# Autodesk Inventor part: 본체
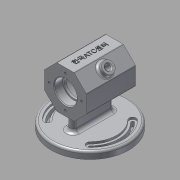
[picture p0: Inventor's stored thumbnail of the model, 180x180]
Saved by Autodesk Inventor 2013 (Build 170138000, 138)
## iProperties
Created: 2017-06
Part Number: 본체
Material: 알루미늄 6061
Document SubType Name: Modeling
Designer: Administrator
Density: 2.71 g/cm^3
Mass: 656.312 g
Surface Area: 514.605 cm^2
Volume: 242.182 cm^3
Author: Administrator
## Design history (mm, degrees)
sketch "스케치2"
  geometry: L1 (0, 0)-(70, 0); L2 (0, 17)-(0, 30); L3 (0, 30)-(70, 30); L4 (70, 17)-(70, 30); L5 (1, 16)-(11.7, 16); L6 (12, 15.7)-(12, 14); L7 (12, 14)-(15, 14); L8 (15, 14)-(15, 22); L9 (18, 25)-(52, 25); L10 (55, 22)-(55, 14); L11 (55, 14)-(58, 14); L12 (58, 14)-(58, 15.7); L13 (58.3, 16)-(69, 16); L14 (0, 17)-(1, 16); L15 (70, 17)-(69, 16); A1 r 3 centre (52, 22) between (55, 22) and (52, 25); A2 r 3 centre (18, 22) between (18, 25) and (15, 22); A3 r 0.3 centre (58.3, 15.7) between (58.3, 16) and (58, 15.7); A4 r 0.3 centre (11.7, 15.7) between (12, 15.7) and (11.7, 16); 8 further points
  constraints: 30 end point, 14 point on line, 8 point on circle, 8 tangent, 6 parallel, 6 perpendicular, 4 centre point, 1 collinear, 1 equal radius, 1 horizontal
  dimensions: "d0" = 70 distance of L1.start L1.end; "d1" = 60 diameter of L3 L1; "d2" = 32 diameter of L5 L1; "d3" = 28 diameter of L7 L1; "d4" = 12 distance from line of point (0, 16) L6; "d5" = 12 distance of point (70, 16) point (58, 16); "d6" = 32 diameter of L13 L1; "d7" = 28 diameter of L11 L1; "d9" = 40 distance between parallel lines of L10 L8; "d10" = 3 radius of A1; "d11" = 1 distance of L2.start point (0, 16); "d12" = 1 distance of L5.start point (0, 16) (= d11); "d13" = 1 distance of L4.start point (70, 16) (= d11); "d14" = 1 distance of L13.end point (70, 16) (= d13); "d15" = 0.3 distance of point (58.3, 16) point (58, 16); "d16" = 0.3 distance of point (58, 15.7) point (58, 16) (= d15); "d17" = 0.3 distance of point (11.7, 16) point (12, 16) (= d15); "d18" = 0.3 distance of point (12, 15.7) point (12, 16) (= d17); "d148" = 50 diameter of L9 L1; "d160" = 0.3 radius of A3; "d161" = 0.3 radius of A4
revolve "회전1" sketch "스케치2" stored, may be unused: angle "d19" = 90 deg
sketch "스케치7"
  geometry: L1 (0, 0)-(0, 30); L2 (0, 30)-(12.426, 30); L3 (6.506, 15.706)-(12.426, 30); L4 (-6.506, 15.706)-(-12.426, 30); L5 (0, 30)-(-12.426, 30); A1 r 17 centre (0, 0) between (-7.11, 15.442) and (10.381, 13.462) reference; A2 r 17 centre (0, 0) between (10.381, 13.462) and (-7.11, 15.442); A3 r 17 centre (0, 0) between (6.506, 15.706) and (-6.506, 15.706); 1 further point
  constraints: 10 end point, 7 point on circle, 2 centre point, 2 symmetric about line, 1 horizontal, 1 perpendicular, 1 vertical, 1 vertical alignment, 1 other
  dimensions: "d43" = 22.5 deg angle of L3 L1
extrude "돌출3" join sketch "스케치7" distance "d44" = 70; taper "d45" = 0 deg
node "작업 평면1"
sketch "스케치8"
  geometry: C1 r 55 at (0, 35); 1 further point
  constraints: 1 centre point
  dimensions: "d50" = 0 horizontal distance of point (0, 0) C1.centre; "d51" = 35 distance of C1.centre point (0, 0); "d52" = 110 diameter of C1
extrude "돌출4" join sketch "스케치8" distance "d53" = 10; taper "d54" = 0 deg
sketch "스케치9"
  geometry: L1 (0, -24)-(0, 24); L2 (-5, -24)-(-5, 24); L3 (4.951, 24.701)-(4.951, -24.701); C1 r 55 at (0, 0) reference; A1 r 5 centre (0, -24) between (-5, -24) and (4.951, -24.701); A2 r 5 centre (0, 24) between (-5, 24) and (4.951, 24.701); 1 further point
  constraints: 6 end point, 4 point on circle, 2 centre point, 2 coincident, 1 equal radius, 1 parallel, 1 tangent, 1 vertical
  dimensions: "d56" = 0 distance from line of C1.centre L1; "d57" = 48 distance of L1.start L1.end; "d58" = 24 distance of L1.start C1.centre; "d59" = 10 diameter of A1
extrude "돌출5" join sketch "스케치9" stored distance "d60" = 10; taper "d61" = 0 deg
sketch "스케치10"
  geometry: L1 (-5, -24)-(-5, 24) reference; L2 (4.951, 24.701)-(4.951, -24.701) reference; L3 (0, 0)-(-48, 0); L4 (0, 0)-(48, 0); L5 (0, -24)-(0, 24); L6 (0, 0)-(-5, -5); L7 (-26.87, -26.87)-(-33.941, -33.941); L8 (0, 0)-(-5, 5); L9 (-26.87, 26.87)-(-33.941, 33.941); L10 (0, 0)-(4.951, -4.951); L11 (26.87, -26.87)-(33.941, -33.941); L12 (0, 0)-(4.951, 4.951); L13 (26.87, 26.87)-(33.941, 33.941); C1 r 55 at (0, 0) reference; A1 r 5 centre (0, 24) between (4.951, 24.701) and (-5, 24) reference; A2 r 5 centre (0, -24) between (-5, -24) and (4.951, -24.701) reference; A3 r 5 centre (-30.406, -30.406) between (-33.941, -33.941) and (-26.67, -33.73); A4 r 5 centre (-30.406, 30.406) between (-26.87, 26.87) and (-26.67, 33.73); A5 r 5 centre (30.406, -30.406) between (33.941, -33.941) and (26.67, -33.73); A6 r 5 centre (30.406, 30.406) between (26.87, 26.87) and (26.67, 33.73); A7 r 38 centre (0, 0) between (26.87, -26.87) and (26.87, 26.87); A8 r 38 centre (0, 0) between (-26.87, 26.87) and (-26.87, -26.87); A9 r 43 centre (0, 0) between (26.67, -33.73) and (26.67, 33.73); A10 r 43 centre (0, 0) between (-26.67, 33.73) and (-26.67, -33.73); A11 r 48 centre (0, 0) between (33.941, -33.941) and (33.941, 33.941); A12 r 48 centre (0, 0) between (-33.941, 33.941) and (-33.941, -33.941); 1 further point
  constraints: 30 point on circle, 22 end point, 10 centre point, 4 midpoint, 4 point on line, 3 coincident, 3 symmetric about line, 2 perpendicular, 1 collinear
  dimensions: "d67" = 45 deg angle of L3 L7
extrude "돌출6" cut sketch "스케치10" distance "d68" = 3; taper "d69" = 0 deg
node "작업 평면2"
sketch "스케치11"
  geometry: C1 r 8 at (12.426, 35); 1 further point
  constraints: 1 centre point
  dimensions: "d71" = 0 horizontal distance of point (12.426, 0) C1.centre; "d72" = 35 distance of point (12.426, 0) C1.centre; "d73" = 16 diameter of C1
extrude "돌출7" join sketch "스케치11" stored distance "d74" = 10; taper "d75" = 0 deg
sketch "스케치12"
  geometry: C1 r 8 at (0, 0) reference; C2 r 4 at (0, 0); 1 further point
  constraints: 1 centre point, 1 coincident
  dimensions: "d76" = 8 diameter of C2
extrude "돌출8" cut sketch "스케치12" stored distance "d78" = 10; taper "d79" = 0 deg
fillet "모깎기1" dims "d80" = 3, "d84" = 5
sketch "스케치16" dims "d112" = 46
  geometry: C1 r 17 at (12.426, 30) reference; 2 further points
  constraints: 1 coincident, 1 vertical alignment, 2 other
  dimensions: "d114" = 0 horizontal distance of point (12.426, 53) point (12.426, 30)
hole "구멍3" sketch "스케치16" at (12.426, 53) diameter "d115" = 3.242; stored, may be unused: countersink angle "d119" = 90 deg, drill point angle "d121" = 118 deg; dims "d116" = 8, "d117" = 4, "d118" = 2, "d120" = 10
sketch "스케치17" dims "d127" = 46
  geometry: C1 r 17 at (12.426, 30) reference; 2 further points
  constraints: 1 coincident, 1 vertical alignment, 2 other
  dimensions: "d125" = 0 horizontal distance of point (12.426, 30) point (12.426, 7)
hole "구멍4" sketch "스케치17" at (12.426, 7) diameter "d128" = 3.242; stored, may be unused: countersink angle "d132" = 90 deg, drill point angle "d134" = 118 deg; dims "d129" = 8, "d130" = 4, "d131" = 2, "d133" = 10
sketch "스케치18"
  geometry: L1 (24.853, 0)-(0, 0) reference; L2 (4.194, 2.871)-(4.194, 67.129); L3 (4.194, 67.129)-(20.659, 67.129); L4 (20.659, 67.129)-(20.659, 2.871); L5 (20.659, 2.871)-(4.194, 2.871); L6 (4.194, 35)-(20.659, 35); L7 (12.426, 2.871)-(12.426, 67.129); L8 (-17.574, 0)-(-17.574, 70) reference; 1 further point
  constraints: 4 end point, 4 midpoint, 2 other
  dimensions: "d138" = 30 distance between parallel lines of L8 L7; "d139" = 35 distance between parallel lines of L6 L1
feature "엠보싱1" sketch "스케치18" dims "d0" = 70, "d1" = 60, "d2" = 32, "d3" = 28, "d4" = 12, "d5" = 12, "d6" = 32, "d7" = 28, "d9" = 40, "d10" = 3, "d11" = 1, "d12" = 1 (= d11), "d13" = 1 (= d11), "d14" = 1 (= d13), "d15" = 0.3, "d16" = 0.3 (= d15), "d17" = 0.3 (= d15), "d18" = 0.3 (= d17), "d140" = 0.5, "d141" = 0, "d148" = 50, "d160" = 0.3, "d161" = 0.3
sketch "스케치20"
  geometry: A1 r 5 centre (-30.406, -30.406) between (-33.941, -33.941) and (-26.87, -26.87) reference; A2 r 5 centre (-30.406, 30.406) between (-26.87, 26.87) and (-33.941, 33.941) reference; A3 r 48 centre (0, 0) between (33.941, -33.941) and (33.941, 33.941) reference; A4 r 5 centre (30.406, 30.406) between (33.941, 33.941) and (26.87, 26.87) reference; A5 r 38 centre (0, 0) between (26.87, -26.87) and (26.87, 26.87) reference; A6 r 5 centre (30.406, -30.406) between (26.87, -26.87) and (33.941, -33.941) reference; A7 r 2 centre (-30.406, -30.406) between (-31.82, -31.82) and (-28.959, -31.787); A8 r 2 centre (-30.406, 30.406) between (-31.82, 31.82) and (-28.959, 31.787); A9 r 2 centre (30.406, -30.406) between (28.991, -28.991) and (28.959, -31.787); A10 r 2 centre (30.406, 30.406) between (28.991, 28.991) and (28.959, 31.787); A11 r 41 centre (0, 0) between (28.991, -28.991) and (28.991, 28.991); A12 r 41 centre (0, 0) between (-28.991, 28.991) and (-28.991, -28.991); A13 r 43 centre (0, 0) between (28.959, -31.787) and (28.959, 31.787); A14 r 43 centre (0, 0) between (-28.959, 31.787) and (-28.959, -31.787); A15 r 45 centre (0, 0) between (31.82, -31.82) and (31.82, 31.82); A16 r 45 centre (0, 0) between (-31.82, 31.82) and (-31.82, -31.82); 1 further point
  constraints: 25 point on circle, 10 centre point, 5 coincident, 3 equal radius
  dimensions: "d142" = 4 diameter of A7
extrude "돌출9" cut sketch "스케치20" distance "d146" = 7; taper "d147" = 0 deg
node "작업 평면3"
sketch "스케치22"
  geometry: C1 r 25 at (12.426, 30); 1 further point
  constraints: 1 centre point, 1 coincident
  dimensions: "d149" = 50 diameter of C1
extrude "돌출10" cut sketch "스케치22" stored distance "d151" = 40; taper "d152" = 0 deg
chamfer "모따기2" distance "d153" = 1; stored, may be unused: second distance "d154" = 2, angle "d155" = 45 deg
fillet "모깎기2" dims "d159" = 1
node "솔리드1"
pattern_circular "원형 패턴1" dims angle "d47" = 360 deg
pattern_circular "원형 패턴4" dims angle "d123" = 360 deg
pattern_circular "원형 패턴5" dims angle "d136" = 360 deg
node "투영된 루프4"
other parameters: "d49" = -62, "d62" = 86, "d64" = 76, "d65" = 96, "d66" = 45 deg, "d70" = 7, "d144" = 2, "d145" = 2
